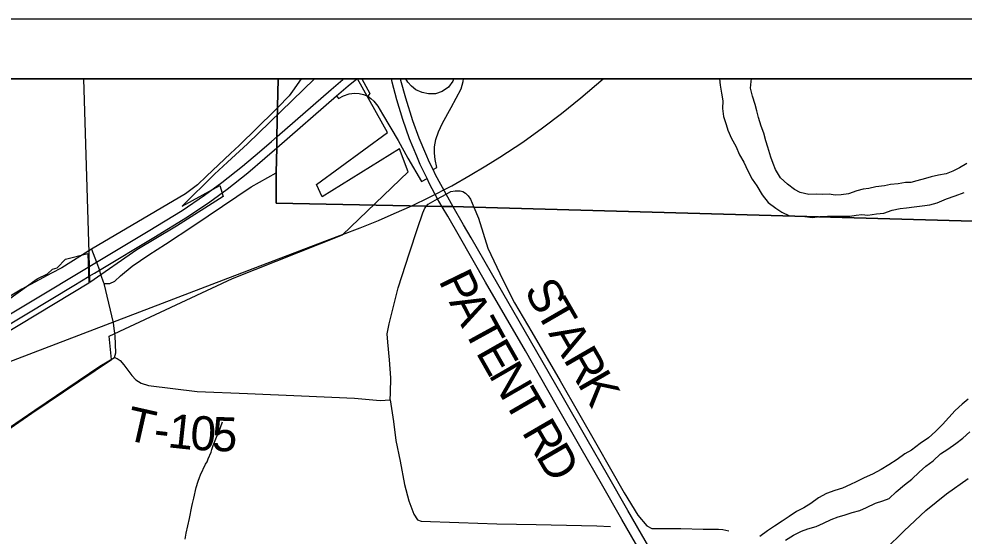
# Model space of a CAD drawing. Extents: x -14196 to 143, y -6096 to 28.
# Drawn here: x 59.995 to 61.569, y 22.937 to 23.799 of the extents above; entities that cross this region are included whole.
import ezdxf

# ---------------------------------------------------------------- set-up
doc = ezdxf.new("R2010")
doc.units = 0
for name, color, linetype in [('GM_X_City_Street', 7, 'Continuous'), ('GM_X_Corporation', 7, 'Continuous'), ('GM_X_County_Road', 7, 'Continuous'), ('GM_X_Interchange_Ramps', 7, 'Continuous'), ('GM_X_Interstate_Route', 7, 'Continuous'), ('GM_X_Major_River', 7, 'Continuous'), ('GM_X_Minor_River', 7, 'Continuous'), ('GM_X_Rail_Line', 7, 'Continuous'), ('GM_X_Township_Road', 7, 'Continuous'), ('GM_X_Township_Road_Text', 7, 'Continuous'), ('GM_X_US_Route', 7, 'Continuous'), ('SH_Data', 7, 'Continuous')]:
    doc.layers.add(name, color=color, linetype=linetype)

msp = doc.modelspace()

# ---------------------------------------------------------------- linework, layer by layer
at = {"layer": 'GM_X_City_Street'}
msp.add_lwpolyline([(60.1367, 23.3574), (60.1462, 23.3578), (60.1546, 23.3614), (60.1641, 23.3702), (60.1834, 23.3866), (60.211, 23.4053), (60.2392, 23.423), (60.286, 23.454), (60.3816, 23.5188), (60.4235, 23.542)], dxfattribs=at)
at = {"layer": 'GM_X_Corporation'}
for points in [[(64.9028, 18.7286), (64.9028, 23.6985), (58.1028, 23.6985), (58.1028, 18.8711)], [(62.1999, 18.7816), (62.2235, 19.866), (62.2323, 20.4208), (62.2487, 21.1358), (62.2751, 22.2884), (62.2815, 22.5484), (62.2824, 22.5866), (62.306, 23.4402), (61.9207, 23.4521), (60.7524, 23.485), (60.7179, 23.4857), (60.6994, 23.486), (60.6731, 23.4865), (60.4232, 23.4912), (60.4233, 23.5426), (60.4242, 23.5839), (60.4246, 23.6029), (60.4257, 23.6513), (60.4267, 23.6985), (58.1028, 23.6985), (58.1028, 18.8711)], [(59.8115, 22.9996), (60.0163, 23.1416), (60.149, 23.231), (60.1454, 23.2699), (60.3506, 23.3657), (60.5336, 23.4389), (60.643, 23.5439), (60.6285, 23.5819), (60.4998, 23.5019), (60.4903, 23.5226), (60.6087, 23.609), (60.5589, 23.6985), (60.4871, 23.6985), (60.3757, 23.5905), (60.342, 23.5596), (60.3207, 23.54), (60.2666, 23.4864), (60.3297, 23.5206), (60.3349, 23.5025), (60.2571, 23.4532), (60.1911, 23.4135), (60.1131, 23.3592), (60.1117, 23.4086), (60.1032, 23.6985), (59.8377, 23.6985)], [(59.9614, 23.3195), (60.0253, 23.3655), (60.0424, 23.3737), (60.0507, 23.3817), (60.0585, 23.3836), (60.0722, 23.3981), (60.1096, 23.4075), (60.1112, 23.3581), (59.9367, 23.2529)]]:
    msp.add_lwpolyline(points, dxfattribs=at)
msp.add_lwpolyline([(62.6174, 23.6985), (60.4267, 23.6985), (60.4257, 23.6513), (60.4246, 23.6029), (60.4242, 23.5839), (60.4233, 23.5426), (60.4232, 23.4912), (60.6731, 23.4865), (60.6994, 23.486), (60.7179, 23.4857), (60.7524, 23.485), (61.9207, 23.4521), (62.306, 23.4402), (62.6129, 23.4358)], close=True, dxfattribs=at)
at = {"layer": 'GM_X_County_Road'}
for points in [[(60.136, 23.3595), (60.132, 23.3707), (60.1292, 23.38)], [(60.1529, 23.287), (60.1522, 23.2921), (60.1367, 23.3574), (60.136, 23.3595)], [(60.0212, 23.1464), (60.1295, 23.2199), (60.154, 23.234), (60.1565, 23.242), (60.1551, 23.2706), (60.1529, 23.287)], [(59.9222, 23.078), (59.9237, 23.0791), (59.9574, 23.1026), (59.9684, 23.1105), (60.0212, 23.1464)], [(61.3247, 22.5353), (61.3237, 22.547), (61.3195, 22.6108), (61.3202, 22.6499), (61.3201, 22.6818), (61.3194, 22.7103), (61.3203, 22.7263), (61.3266, 22.7442), (61.3403, 22.7683), (61.3645, 22.8104), (61.3858, 22.8411), (61.4086, 22.876), (61.4224, 22.9009), (61.4374, 22.914), (61.4694, 22.9452), (61.5055, 22.9791), (61.5398, 23.0069), (61.576, 23.0325)]]:
    msp.add_lwpolyline(points, dxfattribs=at)
at = {"layer": 'GM_X_Interchange_Ramps'}
msp.add_line((60.5334, 23.6985), (60.5342, 23.6976), dxfattribs=at)
for points in [[(60.5659, 23.6985), (60.5793, 23.6742), (60.5758, 23.6695)], [(60.7189, 23.6985), (60.7178, 23.6948), (60.7102, 23.6845), (60.6998, 23.6777), (60.6885, 23.6739), (60.6771, 23.6738), (60.6665, 23.6757), (60.6558, 23.6805), (60.6485, 23.6865), (60.6428, 23.6931), (60.6392, 23.6985)], [(60.685, 23.5475), (60.691, 23.5509), (60.6879, 23.564), (60.687, 23.5747), (60.6872, 23.5852), (60.6893, 23.5976), (60.6935, 23.6101), (60.7004, 23.6247), (60.715, 23.6507), (60.7312, 23.6817), (60.735, 23.6943), (60.7356, 23.6985)], [(60.5236, 23.6703), (60.5272, 23.6659), (60.5354, 23.6702), (60.5449, 23.6734), (60.5539, 23.6745), (60.5615, 23.6743), (60.5688, 23.6724), (60.5758, 23.6695)], [(60.5758, 23.6695), (60.5811, 23.6658), (60.5859, 23.6615), (60.5928, 23.6532), (60.6007, 23.6397), (60.6266, 23.5959), (60.6424, 23.5663), (60.6655, 23.5278), (60.675, 23.5323)]]:
    msp.add_lwpolyline(points, dxfattribs=at)
at = {"layer": 'GM_X_Interstate_Route'}
for points in [[(60.675, 23.5323), (60.6632, 23.5558), (60.6575, 23.5698), (60.6455, 23.5989), (60.6343, 23.6307), (60.6245, 23.6636), (60.6165, 23.6929), (60.6152, 23.6985)], [(60.685, 23.5475), (60.6789, 23.559), (60.6727, 23.5738), (60.6613, 23.6), (60.6508, 23.6289), (60.6391, 23.6664), (60.6312, 23.6957), (60.6306, 23.6985)], [(60.748, 23.4334), (60.7354, 23.4552), (60.7181, 23.4851), (60.7062, 23.5063), (60.6888, 23.5389), (60.685, 23.5475)], [(61.0447, 22.8852), (60.9993, 22.964), (60.965, 23.0237), (60.9313, 23.0824), (60.8895, 23.1551), (60.8384, 23.2451), (60.7719, 23.3597), (60.7287, 23.4361), (60.709, 23.4698), (60.6996, 23.4855), (60.6923, 23.4988), (60.6788, 23.5238), (60.675, 23.5323)], [(61.2138, 22.6226), (61.1749, 22.6914), (61.1387, 22.7538), (61.0895, 22.839), (61.0547, 22.9004), (61.0093, 22.9791), (60.975, 23.0389), (60.9413, 23.0976), (60.8995, 23.1703), (60.8467, 23.2618), (60.7819, 23.3749), (60.748, 23.4334)]]:
    msp.add_lwpolyline(points, dxfattribs=at)
at = {"layer": 'GM_X_Major_River'}
for points in [[(61.162, 23.6985), (61.163, 23.6883), (61.1651, 23.6747), (61.1672, 23.6618), (61.1669, 23.6493), (61.1682, 23.636), (61.1726, 23.6228), (61.1754, 23.6129), (61.1816, 23.5993), (61.189, 23.5865), (61.1948, 23.5722), (61.2022, 23.5597), (61.2092, 23.5454), (61.2162, 23.5314), (61.224, 23.5201), (61.2329, 23.5051), (61.2429, 23.4923), (61.2555, 23.4833), (61.2655, 23.4762), (61.2785, 23.4703), (61.2902, 23.4697), (61.3039, 23.4691), (61.3168, 23.4678), (61.3289, 23.469), (61.3414, 23.47), (61.3536, 23.4697), (61.368, 23.4695), (61.379, 23.4697), (61.3892, 23.4713), (61.3987, 23.4726), (61.409, 23.4715), (61.423, 23.4736), (61.4355, 23.4749), (61.4491, 23.4796), (61.4627, 23.4824), (61.4733, 23.4837), (61.4858, 23.4854), (61.4995, 23.4871), (61.5123, 23.4888), (61.5244, 23.4919), (61.5399, 23.4986), (61.5543, 23.5037), (61.5694, 23.5092)], [(61.5737, 23.5578), (61.5613, 23.5501), (61.5503, 23.5446), (61.539, 23.5403), (61.5265, 23.5379), (61.5144, 23.5355), (61.5046, 23.5327), (61.4906, 23.5287), (61.4807, 23.5259), (61.4713, 23.5258), (61.4591, 23.5238), (61.4466, 23.5225), (61.4364, 23.5205), (61.4224, 23.5188), (61.4103, 23.516), (61.4008, 23.5147), (61.3906, 23.5119), (61.3766, 23.5072), (61.3645, 23.5055), (61.3543, 23.5047), (61.3444, 23.5064), (61.3326, 23.5059), (61.3232, 23.5062), (61.3106, 23.506), (61.2962, 23.5093), (61.2866, 23.5141), (61.2751, 23.523), (61.2636, 23.5339), (61.2551, 23.5475), (61.2512, 23.5573), (61.2473, 23.5683), (61.2425, 23.5845), (61.2389, 23.5951), (61.2357, 23.6083), (61.231, 23.6197), (61.2267, 23.634), (61.2239, 23.6454), (61.2211, 23.656), (61.2168, 23.67), (61.2136, 23.6832), (61.2146, 23.6943), (61.215, 23.6985)], [(61.576, 23.165), (61.5662, 23.1565), (61.5542, 23.1461), (61.5333, 23.1223), (61.5213, 23.1108), (61.51, 23.1004), (61.4961, 23.0908), (61.4818, 23.0796), (61.4702, 23.0737), (61.4574, 23.0645), (61.4438, 23.0556), (61.431, 23.0475), (61.4163, 23.0397), (61.4028, 23.0334), (61.3896, 23.0272), (61.3797, 23.0225), (61.3665, 23.0163), (61.3541, 23.0123), (61.3401, 23.0076), (61.3269, 23.0006), (61.3137, 22.991), (61.3021, 22.9836), (61.29, 22.9774), (61.278, 22.9693), (61.2663, 22.9612), (61.2535, 22.953), (61.2419, 22.9453), (61.2287, 22.9357)], [(61.2717, 22.9297), (61.2852, 22.9382), (61.2984, 22.9449), (61.3086, 22.9484), (61.323, 22.9528), (61.3347, 22.9582), (61.3475, 22.9644), (61.3596, 22.9684), (61.3694, 22.9712), (61.3826, 22.9759), (61.3955, 22.9795), (61.4068, 22.9845), (61.4215, 22.9912), (61.434, 22.9951), (61.4445, 22.9994), (61.4562, 23.0102), (61.4697, 23.0221), (61.4821, 23.0314), (61.4941, 23.0429), (61.5053, 23.0533), (61.5177, 23.0622), (61.5297, 23.0737), (61.5418, 23.0815), (61.5553, 23.0911), (61.567, 23.1), (61.5786, 23.1104)]]:
    msp.add_lwpolyline(points, dxfattribs=at)
at = {"layer": 'GM_X_Minor_River'}
msp.add_lwpolyline([(60.2718, 22.9314), (60.2733, 22.9413), (60.2787, 22.966), (60.2827, 22.9858), (60.2842, 22.9908), (60.286, 22.9999), (60.29, 23.0178), (60.2933, 23.0281), (60.2959, 23.0342), (60.2974, 23.0388), (60.3056, 23.0564), (60.3082, 23.0606), (60.31, 23.0655), (60.3153, 23.0762), (60.3164, 23.0808), (60.3186, 23.0873), (60.3253, 23.104), (60.3275, 23.1079), (60.3338, 23.1269)], dxfattribs=at)
at = {"layer": 'GM_X_Rail_Line'}
msp.add_lwpolyline([(58.1028, 22.5102), (58.5061, 22.6648), (59.0457, 22.8709), (59.6972, 23.1194), (60.0189, 23.2424), (60.3358, 23.3635), (60.5045, 23.428), (60.5632, 23.4504), (60.5938, 23.4628), (60.6201, 23.474), (60.6495, 23.4872), (60.6788, 23.5017), (60.7158, 23.5204), (60.7465, 23.5379), (60.7724, 23.5535), (60.7959, 23.5682), (60.8339, 23.5931), (60.8671, 23.6168), (60.8984, 23.6407), (60.9307, 23.6668), (60.9677, 23.6985)], dxfattribs=at)
at = {"layer": 'GM_X_Township_Road'}
msp.add_line((60.4652, 23.6985), (60.4507, 23.6783), dxfattribs=at)
for points in [[(60.4507, 23.6783), (60.4449, 23.6702), (60.4259, 23.6507), (60.4213, 23.646), (60.3616, 23.5876), (60.3473, 23.5741)], [(60.3473, 23.5741), (60.3075, 23.5363), (60.2923, 23.5222), (60.2721, 23.5069), (60.2225, 23.4774), (60.116, 23.4146), (60.1242, 23.3933), (60.1292, 23.38)], [(60.154, 23.234), (60.1586, 23.2323), (60.1634, 23.229), (60.1696, 23.2218), (60.1829, 23.2042), (60.1898, 23.197), (60.1985, 23.1917), (60.2107, 23.1878), (60.2917, 23.1778), (60.3754, 23.1743), (60.4657, 23.1706), (60.5536, 23.1664), (60.5963, 23.1628), (60.6134, 23.1638), (60.6136, 23.1752), (60.6141, 23.2003), (60.6122, 23.2306), (60.6091, 23.2595), (60.6082, 23.2735), (60.6118, 23.2903), (60.6266, 23.3501), (60.6453, 23.4085), (60.6589, 23.4491), (60.6675, 23.4755), (60.6707, 23.4829), (60.6733, 23.486), (60.6763, 23.4897), (60.6803, 23.4922), (60.6923, 23.4988), (60.7062, 23.5063), (60.7144, 23.5108), (60.7216, 23.5122), (60.7297, 23.5122), (60.7343, 23.5108), (60.7388, 23.508), (60.7431, 23.5037), (60.7469, 23.4983), (60.7527, 23.4845), (60.7602, 23.4664), (60.7761, 23.4163), (60.8011, 23.3634), (60.8203, 23.3253), (60.849, 23.2766), (60.8965, 23.1956), (60.9576, 23.0885), (61.0028, 23.0085), (61.0257, 22.9712), (61.0408, 22.9536), (61.0488, 22.9495), (61.0701, 22.9494), (61.0971, 22.9494), (61.1344, 22.9483), (61.1603, 22.9483), (61.1672, 22.9476), (61.1771, 22.9455)], [(60.116, 23.4146), (60.0661, 23.3834), (60.049, 23.3749), (60.0211, 23.36), (59.9995, 23.348), (59.9776, 23.3348), (59.9591, 23.3228), (59.924, 23.2999), (59.8691, 23.2651), (59.8575, 23.2592), (59.8497, 23.2585), (59.8481, 23.2594)], [(60.6134, 23.1638), (60.6188, 23.1277), (60.6226, 23.0959), (60.6296, 23.0614), (60.6373, 23.0224), (60.6441, 22.9955), (60.6524, 22.9732), (60.659, 22.9638), (60.6651, 22.9612), (60.7275, 22.959), (60.7911, 22.9571), (60.8562, 22.9561), (60.9319, 22.954), (60.9574, 22.9536), (60.9803, 22.9524)]]:
    msp.add_lwpolyline(points, dxfattribs=at)
at = {"layer": 'GM_X_US_Route'}
for p, q in [((60.0863, 23.3541), (60.1121, 23.3696)), ((60.1121, 23.3696), (60.1207, 23.3748))]:
    msp.add_line(p, q, dxfattribs=at)
for points in [[(60.1242, 23.3933), (60.2104, 23.4449), (60.2666, 23.4792), (60.3039, 23.5046), (60.3328, 23.5256), (60.3673, 23.553), (60.3957, 23.5771), (60.4155, 23.5942), (60.4249, 23.6024), (60.5147, 23.6811), (60.5342, 23.6976), (60.5355, 23.6985)], [(60.5236, 23.6703), (60.5432, 23.6868), (60.5578, 23.6985)], [(60.1207, 23.3748), (60.1292, 23.38), (60.2194, 23.4341), (60.2756, 23.4685), (60.3129, 23.4938), (60.3417, 23.5148), (60.3763, 23.5422), (60.4046, 23.5664), (60.4244, 23.5834), (60.5236, 23.6703)], [(59.3404, 23.0726), (59.417, 23.0847), (59.4769, 23.0925), (59.5189, 23.0987), (59.5566, 23.1062), (59.5893, 23.114), (59.614, 23.1205), (59.6375, 23.1278), (59.6694, 23.1385), (59.7015, 23.1511), (59.7368, 23.1663), (59.7736, 23.1844), (59.8165, 23.2085), (59.8631, 23.2364), (60.0032, 23.3203), (60.1242, 23.3933)], [(59.1432, 23.0399), (59.1998, 23.0465), (59.482, 23.0792), (59.524, 23.0854), (59.5617, 23.0929), (59.5944, 23.1008), (59.6191, 23.1072), (59.6426, 23.1145), (59.6745, 23.1253), (59.7066, 23.1378), (59.7419, 23.153), (59.7787, 23.1711), (59.8216, 23.1953), (59.8682, 23.2231), (60.0083, 23.307), (60.0863, 23.3541)]]:
    msp.add_lwpolyline(points, dxfattribs=at)
at = {"layer": 'SH_Data'}
for p, q in [((58.0028, 23.7985), (65.0028, 23.7985)), ((58.1028, 23.6985), (64.9028, 23.6985))]:
    msp.add_line(p, q, dxfattribs=at)

# ---------------------------------------------------------------- texts
at = {"layer": 'GM_X_Township_Road_Text'}
for s, rotation, p in [('P', 295.951, (60.6931, 23.3625)), ('S', 298.5054, (60.8355, 23.3466)), ('A', 297.3077, (60.7105, 23.3267)), ('T', 300.0055, (60.8546, 23.3115)), ('T', 298.7233, (60.7342, 23.2809)), ('A', 300.0387, (60.8759, 23.2746)), ('E', 299.6066, (60.7551, 23.2428)), ('R', 300.0407, (60.9009, 23.2313)), ('N', 300.0444, (60.7763, 23.2054)), ('K', 300.0404, (60.9243, 23.1909)), ('T', 300.1327, (60.8014, 23.1621)), ('T', 347.2216, (60.1696, 23.098)), ('1', 353.8275, (60.2413, 23.0848)), ('0', 356.6688, (60.2792, 23.0808)), ('5', 357.977, (60.3155, 23.0787)), ('R', 300.1351, (60.8315, 23.1102)), ('-', 353.3863, (60.2176, 23.0875)), ('D', 300.1335, (60.8549, 23.0698))]:
    msp.add_text(s, height=0.0568, rotation=rotation, dxfattribs=at).set_placement(p)

doc.saveas('drawing.dxf')
